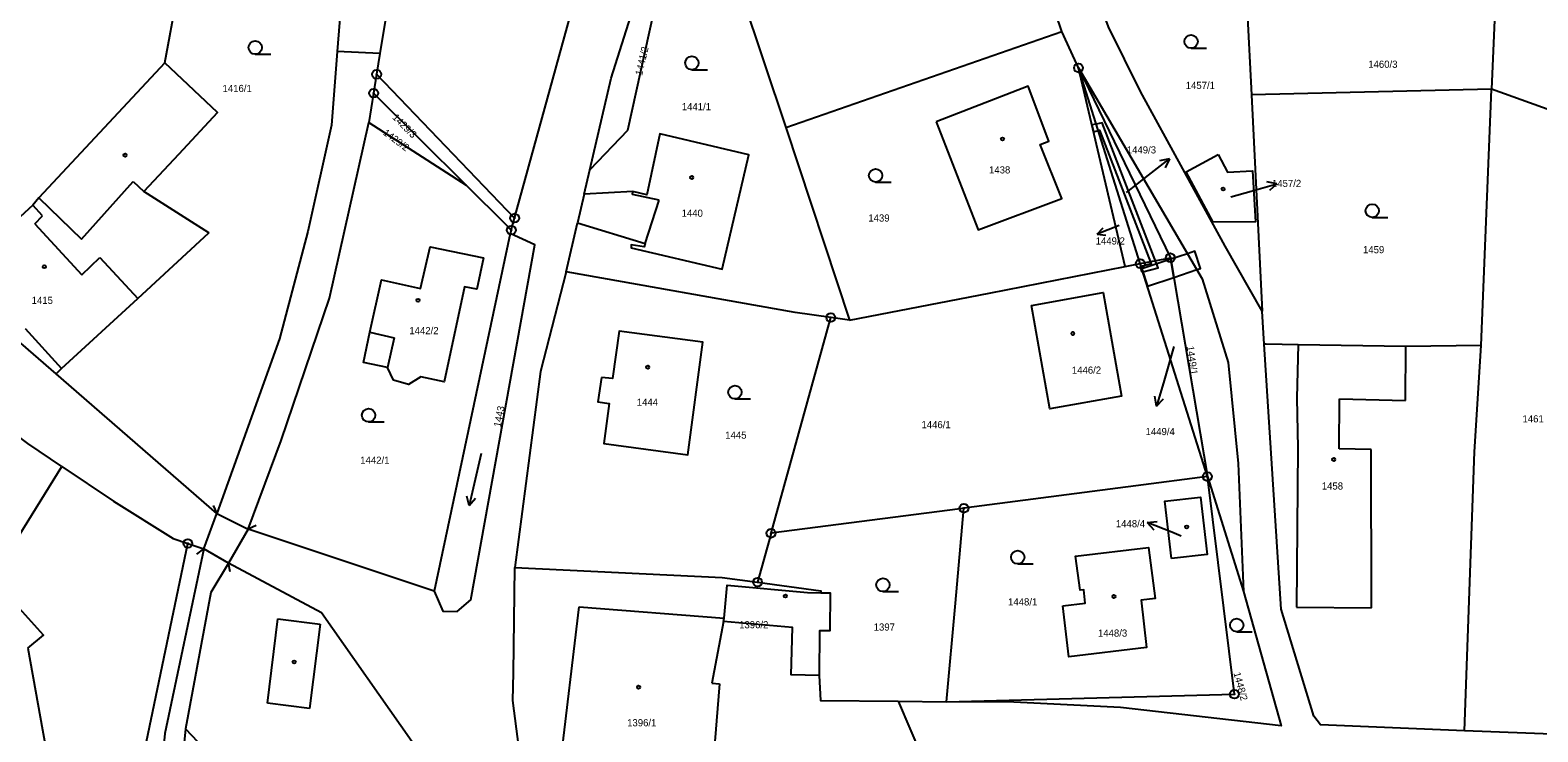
# Model space of a CAD drawing. Extents: x -587171 to -555306, y -1167727 to -1074732.
# Drawn here: x -559900.1 to -559730.7, y -1076166.3 to -1076087.4 of the extents above; entities that cross this region are included whole.
import ezdxf

# ---------------------------------------------------------------- set-up
doc = ezdxf.new("R2010")
doc.units = 0
for name, color, linetype in [('Hranice parcel', 7, 'Continuous'), ('Parcelní čísla', 7, 'Continuous'), ('Pop  PČ popisy', 7, 'Continuous'), ('Vnitřní kresba', 7, 'Continuous'), ('Věcná břemena k části', 7, 'Continuous'), ('Značky bodu BP', 7, 'Continuous'), ('Značky budov', 7, 'Continuous'), ('Značky kultur', 7, 'Continuous')]:
    doc.layers.add(name, color=color, linetype=linetype)

msp = doc.modelspace()

# ---------------------------------------------------------------- linework, layer by layer
at = {"layer": 'Hranice parcel'}
for p, q in [((-559884.99, -1076091.09), (-559876, -1076041.64)), ((-559834.85, -1076092.79), (-559826.2, -1076065.36)), ((-559784.21, -1076087.54), (-559791.91, -1076064.81)), ((-559822.86, -1076075.59), (-559815.22, -1076098.33)), ((-559865.19, -1076084.2), (-559865.63, -1076089.8)), ((-559763.38, -1076085.21), (-559762.91, -1076094.66)), ((-559735.54, -1076084.55), (-559735.95, -1076094.02)), ((-559845.7, -1076108.53), (-559839.49, -1076085.97)), ((-559815.22, -1076098.33), (-559784.21, -1076087.54)), ((-559782.34, -1076091.64), (-559784.21, -1076087.54)), ((-559860.82, -1076090.03), (-559865.63, -1076089.8)), ((-559860.82, -1076090.03), (-559861.2, -1076092.36)), ((-559861.2, -1076092.36), (-559861.54, -1076094.48)), ((-559861.2, -1076092.36), (-559845.7, -1076108.53)), ((-559777.09, -1076113.98), (-559782.34, -1076091.64)), ((-559782.34, -1076091.64), (-559772.01, -1076112.99)), ((-559775.4, -1076113.65), (-559782.34, -1076091.64)), ((-559837.24, -1076103.11), (-559834.85, -1076092.79)), ((-559735.95, -1076094.02), (-559762.91, -1076094.66)), ((-559737.09, -1076122.84), (-559735.95, -1076094.02)), ((-559722.33, -1076098.92), (-559735.95, -1076094.02)), ((-559861.54, -1076094.48), (-559862.08, -1076097.79)), ((-559851.15, -1076104.82), (-559861.54, -1076094.48)), ((-559762.91, -1076094.66), (-559761.69, -1076119.01)), ((-559862.08, -1076097.79), (-559851.15, -1076104.82)), ((-559815.22, -1076098.33), (-559808.08, -1076120.01)), ((-559837.88, -1076105.85), (-559837.24, -1076103.11)), ((-559837.88, -1076105.85), (-559838.63, -1076109.06)), ((-559846.07, -1076109.88), (-559845.7, -1076108.53)), ((-559839.91, -1076114.56), (-559838.63, -1076109.06)), ((-559846.18, -1076110.27), (-559854.72, -1076150.48)), ((-559846.07, -1076109.88), (-559846.18, -1076110.27)), ((-559777.09, -1076113.98), (-559775.4, -1076113.65)), ((-559775.4, -1076113.65), (-559772.01, -1076112.99)), ((-559767.86, -1076137.59), (-559775.4, -1076113.65)), ((-559772.01, -1076112.99), (-559767.86, -1076137.59)), ((-559816.88, -1076143.96), (-559810.17, -1076119.71)), ((-559808.08, -1076120.01), (-559810.17, -1076119.71)), ((-559761.46, -1076122.7), (-559761.69, -1076119.01)), ((-559879.16, -1076141.75), (-559897.21, -1076126.04)), ((-559767.86, -1076137.59), (-559763.79, -1076150.5)), ((-559880.6, -1076145.7), (-559879.16, -1076141.75)), ((-559882.41, -1076145.11), (-559880.6, -1076145.7)), ((-559875.64, -1076143.51), (-559877.86, -1076147.32)), ((-559854.72, -1076150.48), (-559875.64, -1076143.51)), ((-559816.88, -1076143.96), (-559818.4, -1076149.46)), ((-559802.6, -1076162.85), (-559797.17, -1076162.9)), ((-559802.6, -1076162.85), (-559799.97, -1076168.98)), ((-559882.67, -1076165.97), (-559883.32, -1076172.76)), ((-559728.16, -1076166.58), (-559738.97, -1076166.19))]:
    msp.add_line(p, q, dxfattribs=at)
for points in [[(-559855.87, -1076062.7), (-559859.56, -1076082.28), (-559860.82, -1076090.03)], [(-559826.2, -1076065.36), (-559827.24, -1076072.43), (-559833, -1076098.69), (-559837.24, -1076103.11)], [(-559761.69, -1076119.01), (-559765.87, -1076111.68), (-559775.38, -1076094.3), (-559778.98, -1076087.02), (-559785.45, -1076069.69)], [(-559865.63, -1076089.8), (-559866.28, -1076098.09), (-559868.93, -1076110.02), (-559872.1, -1076122.11), (-559879.16, -1076141.75)], [(-559884.99, -1076091.09), (-559899.17, -1076106.24), (-559899.82, -1076107.06), (-559900.76, -1076107.92), (-559907.17, -1076113.84)], [(-559897.21, -1076126.04), (-559896.61, -1076125.44), (-559888.04, -1076117.57), (-559880.04, -1076110.2), (-559882.41, -1076108.7), (-559887.36, -1076105.55), (-559883.4, -1076101.31), (-559879.06, -1076096.66), (-559884.99, -1076091.09)], [(-559782.34, -1076091.64), (-559768.44, -1076115.37), (-559765.53, -1076124.77), (-559764.41, -1076136.13), (-559763.79, -1076150.5)], [(-559798.34, -1076097.72), (-559793.61, -1076109.84), (-559784.2, -1076106.32), (-559786.63, -1076100.24), (-559785.66, -1076099.87), (-559787.99, -1076093.7), (-559798.34, -1076097.72)], [(-559875.64, -1076143.51), (-559871.92, -1076133.55), (-559866.48, -1076117.52), (-559862.08, -1076097.79)], [(-559838.63, -1076109.06), (-559831.02, -1076111.38), (-559831.14, -1076111.76), (-559832.59, -1076111.55), (-559832.59, -1076111.87), (-559822.38, -1076114.26), (-559819.38, -1076101.42), (-559829.39, -1076099.07), (-559830.85, -1076105.9), (-559832.42, -1076105.53), (-559837.88, -1076105.85)], [(-559766.66, -1076101.37), (-559765.6, -1076103.38), (-559762.77, -1076103.22), (-559762.45, -1076108.94), (-559767.19, -1076108.98), (-559770.25, -1076103.32), (-559766.66, -1076101.37)], [(-559851.15, -1076104.82), (-559846.63, -1076109.29), (-559846.07, -1076109.88)], [(-559854.72, -1076150.48), (-559853.77, -1076152.72), (-559852.14, -1076152.78), (-559850.63, -1076151.46), (-559843.43, -1076111.52), (-559846.18, -1076110.27)], [(-559849.2, -1076112.99), (-559849.94, -1076116.52), (-559851.34, -1076116.26), (-559853.61, -1076126.93), (-559856.24, -1076126.37), (-559857.6, -1076127.23), (-559859.32, -1076126.76), (-559859.96, -1076125.33), (-559862.69, -1076124.76), (-559861.98, -1076121.35), (-559860.64, -1076115.48), (-559856.27, -1076116.46), (-559855.18, -1076111.75), (-559849.2, -1076112.99)], [(-559897.21, -1076126.04), (-559901.72, -1076122.11), (-559907.17, -1076113.84)], [(-559839.91, -1076114.56), (-559842.79, -1076125.76), (-559845.67, -1076147.82)], [(-559810.17, -1076119.71), (-559814.16, -1076119.13), (-559839.91, -1076114.56)], [(-559808.08, -1076120.01), (-559792.37, -1076116.96), (-559777.09, -1076113.98)], [(-559787.62, -1076118.34), (-559779.58, -1076116.91), (-559777.52, -1076128.55), (-559785.57, -1076129.98), (-559787.62, -1076118.34)], [(-559835.94, -1076126.44), (-559836.35, -1076129.19), (-559835.06, -1076129.36), (-559835.68, -1076133.88), (-559826.23, -1076135.13), (-559824.53, -1076122.48), (-559833.95, -1076121.23), (-559834.68, -1076126.56), (-559835.94, -1076126.44)], [(-559737.09, -1076122.84), (-559745.55, -1076122.95), (-559757.64, -1076122.79), (-559761.24, -1076122.7), (-559761.46, -1076122.7)], [(-559738.97, -1076166.19), (-559755.13, -1076165.51), (-559755.91, -1076164.54), (-559759.55, -1076152.51), (-559761.46, -1076122.7)], [(-559738.97, -1076166.19), (-559737.84, -1076134.82), (-559737.09, -1076122.84)], [(-559896.56, -1076136.45), (-559900.38, -1076133.87), (-559902.61, -1076132.23)], [(-559900.38, -1076156.9), (-559898.63, -1076155.42), (-559904.38, -1076149.06), (-559896.56, -1076136.45)], [(-559896.56, -1076136.45), (-559890.78, -1076140.36), (-559884.05, -1076144.57), (-559882.41, -1076145.11)], [(-559797.17, -1076162.9), (-559764.82, -1076162.06), (-559767.86, -1076137.59)], [(-559767.86, -1076137.59), (-559775.91, -1076138.64), (-559795.21, -1076141.15)], [(-559771.87, -1076146.8), (-559772.65, -1076140.36), (-559768.63, -1076139.89), (-559767.89, -1076146.35), (-559771.87, -1076146.8)], [(-559795.21, -1076141.15), (-559795.63, -1076141.2), (-559816.88, -1076143.96)], [(-559797.17, -1076162.9), (-559796.17, -1076151.81), (-559795.21, -1076141.15)], [(-559884, -1076224.4), (-559882.97, -1076218.43), (-559883.21, -1076209.54), (-559887.76, -1076190.03), (-559888.26, -1076180.76), (-559887.42, -1076169.19), (-559882.41, -1076145.11)], [(-559880.6, -1076145.7), (-559884.99, -1076166.47), (-559886.45, -1076181.35), (-559885.78, -1076187.84), (-559883.56, -1076194.33), (-559880.18, -1076200.87), (-559872.79, -1076210.53), (-559872.01, -1076213.63), (-559872.94, -1076226.45), (-559877.73, -1076234.53)], [(-559784.11, -1076152.12), (-559781.57, -1076151.82), (-559781.74, -1076150.33), (-559782.14, -1076150.37), (-559782.68, -1076146.53), (-559774.48, -1076145.58), (-559773.74, -1076151.29), (-559775.29, -1076151.5), (-559774.71, -1076156.81), (-559783.43, -1076157.84), (-559784.11, -1076152.12)], [(-559877.86, -1076147.32), (-559879.81, -1076150.61), (-559882.67, -1076165.97)], [(-559857.26, -1076167.36), (-559867.39, -1076152.91), (-559877.86, -1076147.32)], [(-559840.08, -1076180.86), (-559843.68, -1076174.89), (-559844.71, -1076172.04), (-559845.91, -1076162.75), (-559845.81, -1076159.66), (-559845.67, -1076147.82)], [(-559845.67, -1076147.82), (-559822.39, -1076148.92), (-559818.4, -1076149.46)], [(-559811.49, -1076159.94), (-559814.62, -1076159.89), (-559814.49, -1076154.56), (-559822.21, -1076153.87), (-559822.14, -1076153.5), (-559821.81, -1076149.79), (-559812.77, -1076150.62), (-559811.3, -1076150.65)], [(-559818.4, -1076149.46), (-559811.3, -1076150.42), (-559811.3, -1076150.65)], [(-559811.3, -1076150.65), (-559810.25, -1076150.68), (-559810.29, -1076154.94), (-559811.43, -1076154.93), (-559811.49, -1076159.94)], [(-559763.79, -1076150.5), (-559759.55, -1076165.6), (-559777.62, -1076163.54), (-559789.59, -1076162.96), (-559797.17, -1076162.9)], [(-559900.38, -1076156.9), (-559890.01, -1076214.69), (-559884, -1076224.4)], [(-559811.49, -1076159.94), (-559811.33, -1076162.78), (-559802.6, -1076162.85)], [(-559882.67, -1076165.97), (-559880.03, -1076168.77), (-559881.21, -1076179.06), (-559868.73, -1076181.16), (-559868.01, -1076175.07), (-559867.5, -1076175.13), (-559863.36, -1076174.42), (-559857.26, -1076167.36)]]:
    msp.add_lwpolyline(points, dxfattribs=at)
at = {"layer": 'Pop  PČ popisy'}
for p, q in [((-559774.49, -1076103.72), (-559772.12, -1076101.87)), ((-559772.12, -1076101.87), (-559773.22, -1076102.09)), ((-559772.12, -1076101.87), (-559772.61, -1076102.88)), ((-559776.93, -1076105.64), (-559774.49, -1076103.72)), ((-559760.06, -1076104.66), (-559761.16, -1076104.46)), ((-559765.22, -1076106.15), (-559762.94, -1076105.49)), ((-559762.94, -1076105.49), (-559760.06, -1076104.66)), ((-559760.06, -1076104.66), (-559760.88, -1076105.42)), ((-559777.78, -1076109.36), (-559780.23, -1076110.35)), ((-559780.23, -1076110.35), (-559779.58, -1076109.61)), ((-559780.23, -1076110.35), (-559779.25, -1076110.43)), ((-559771.63, -1076122.95), (-559772.73, -1076126.78)), ((-559772.73, -1076126.78), (-559773.56, -1076129.67)), ((-559773.56, -1076129.67), (-559773.76, -1076128.56)), ((-559773.56, -1076129.67), (-559772.8, -1076128.84)), ((-559774.62, -1076142.74), (-559773.51, -1076142.65)), ((-559771.84, -1076143.86), (-559774.62, -1076142.74)), ((-559774.62, -1076142.74), (-559773.88, -1076143.57)), ((-559770.81, -1076144.28), (-559771.84, -1076143.86))]:
    msp.add_line(p, q, dxfattribs=at)
at = {"layer": 'Vnitřní kresba'}
for p, q in [((-559894.37, -1076110.88), (-559888.56, -1076104.43)), ((-559888.56, -1076104.43), (-559887.36, -1076105.55)), ((-559832.46, -1076105.86), (-559832.42, -1076105.53)), ((-559829.44, -1076106.51), (-559832.46, -1076105.86)), ((-559898.73, -1076108.27), (-559899.82, -1076107.06)), ((-559899.17, -1076106.24), (-559894.37, -1076110.88)), ((-559831.02, -1076111.38), (-559829.44, -1076106.51)), ((-559899.6, -1076109.18), (-559898.73, -1076108.27)), ((-559899.6, -1076109.18), (-559894.33, -1076114.9)), ((-559894.33, -1076114.9), (-559892.3, -1076112.97)), ((-559892.3, -1076112.97), (-559888.04, -1076117.57)), ((-559900.69, -1076120.95), (-559896.61, -1076125.44)), ((-559861.98, -1076121.35), (-559859.22, -1076121.99)), ((-559859.22, -1076121.99), (-559859.96, -1076125.33)), ((-559757.64, -1076122.79), (-559757.81, -1076128.72)), ((-559745.61, -1076129.04), (-559745.55, -1076122.95)), ((-559757.81, -1076128.72), (-559757.68, -1076134.4)), ((-559753.06, -1076134.48), (-559753.02, -1076128.85)), ((-559753.02, -1076128.85), (-559745.61, -1076129.04)), ((-559757.68, -1076134.4), (-559757.86, -1076152.28)), ((-559749.46, -1076134.53), (-559753.06, -1076134.48)), ((-559749.43, -1076152.35), (-559749.46, -1076134.53)), ((-559879.58, -1076140.84), (-559879.16, -1076141.75)), ((-559879.16, -1076141.75), (-559875.64, -1076143.51)), ((-559874.73, -1076143.1), (-559875.64, -1076143.51)), ((-559881.4, -1076146.3), (-559880.6, -1076145.7)), ((-559877.86, -1076147.32), (-559880.6, -1076145.7)), ((-559877.64, -1076148.29), (-559877.86, -1076147.32)), ((-559873.47, -1076163.07), (-559872.29, -1076153.57)), ((-559872.29, -1076153.57), (-559867.55, -1076154.19)), ((-559840.95, -1076173.22), (-559838.44, -1076152.23)), ((-559838.44, -1076152.23), (-559822.14, -1076153.5)), ((-559757.86, -1076152.28), (-559749.43, -1076152.35)), ((-559867.55, -1076154.19), (-559868.73, -1076163.68)), ((-559822.21, -1076153.87), (-559823.52, -1076160.82)), ((-559822.66, -1076160.89), (-559823.84, -1076175.31)), ((-559823.52, -1076160.82), (-559822.66, -1076160.89)), ((-559868.73, -1076163.68), (-559873.47, -1076163.07))]:
    msp.add_line(p, q, dxfattribs=at)
at = {"layer": 'Věcná břemena k části'}
for points in [[(-559780.12, -1076098.69), (-559779.98, -1076098.66), (-559774.19, -1076113.66), (-559775.3, -1076113.96), (-559775.11, -1076114.56), (-559773.37, -1076114.13), (-559779.67, -1076097.8), (-559780.35, -1076097.95), (-559780.83, -1076098.06), (-559780.65, -1076098.82)], [(-559770.1, -1076112.53), (-559771.98, -1076113.16), (-559771.64, -1076115.19), (-559769.05, -1076114.32), (-559768.63, -1076114.18), (-559769.28, -1076112.25)], [(-559775.24, -1076114.59), (-559775.11, -1076114.56), (-559775.3, -1076113.96), (-559775.4, -1076113.99)], [(-559771.64, -1076115.19), (-559771.98, -1076113.16), (-559775.21, -1076114.25), (-559774.6, -1076116.19)]]:
    msp.add_lwpolyline(points, close=True, dxfattribs=at)
at = {"layer": 'Značky bodu BP'}
for centre, radius in [((-559861.2, -1076092.36), 0.5), ((-559861.2, -1076092.36), 0.0303), ((-559782.34, -1076091.64), 0.5), ((-559782.34, -1076091.64), 0.0303), ((-559861.54, -1076094.48), 0.5), ((-559861.54, -1076094.48), 0.0303), ((-559846.07, -1076109.88), 0.5), ((-559845.7, -1076108.53), 0.5), ((-559845.7, -1076108.53), 0.0303), ((-559846.07, -1076109.88), 0.0303), ((-559772.01, -1076112.99), 0.5), ((-559772.01, -1076112.99), 0.0303), ((-559775.4, -1076113.65), 0.5), ((-559775.4, -1076113.65), 0.0303), ((-559810.17, -1076119.71), 0.5), ((-559810.17, -1076119.71), 0.0303), ((-559767.86, -1076137.59), 0.5), ((-559767.86, -1076137.59), 0.0303), ((-559795.21, -1076141.15), 0.5), ((-559795.21, -1076141.15), 0.0303), ((-559816.88, -1076143.96), 0.5), ((-559882.41, -1076145.11), 0.5), ((-559882.41, -1076145.11), 0.0303), ((-559816.88, -1076143.96), 0.0303), ((-559818.4, -1076149.46), 0.5), ((-559818.4, -1076149.46), 0.0303), ((-559764.82, -1076162.06), 0.5), ((-559764.82, -1076162.06), 0.0303)]:
    msp.add_circle(centre, radius, dxfattribs=at)
at = {"layer": 'Značky budov'}
for centre in [(-559790.88, -1076099.64), (-559889.47, -1076101.45), (-559825.8, -1076103.96), (-559766.09, -1076105.26), (-559898.54, -1076114), (-559856.55, -1076117.77), (-559782.97, -1076121.51), (-559830.74, -1076125.29), (-559753.66, -1076135.67), (-559770.18, -1076143.26), (-559815.27, -1076151.03), (-559778.36, -1076151.07), (-559870.47, -1076158.44), (-559831.76, -1076161.27)]:
    msp.add_circle(centre, 0.175, dxfattribs=at)
at = {"layer": 'Značky kultur'}
for p, q in [((-559874.84, -1076090.1), (-559873.09, -1076090.1)), ((-559769.69, -1076089.43), (-559767.94, -1076089.43)), ((-559825.78, -1076091.84), (-559824.03, -1076091.84)), ((-559805.13, -1076104.49), (-559803.38, -1076104.49)), ((-559749.33, -1076108.45), (-559747.58, -1076108.45)), ((-559820.94, -1076128.86), (-559819.19, -1076128.86)), ((-559862.1, -1076131.45), (-559860.35, -1076131.45)), ((-559849.44, -1076135.01), (-559850.79, -1076140.86)), ((-559850.79, -1076140.86), (-559851.06, -1076139.79)), ((-559850.79, -1076140.86), (-559850.08, -1076140.02)), ((-559789.17, -1076147.41), (-559787.42, -1076147.41)), ((-559804.31, -1076150.52), (-559802.56, -1076150.52)), ((-559764.56, -1076155.05), (-559762.81, -1076155.05))]:
    msp.add_line(p, q, dxfattribs=at)
for centre in [(-559874.84, -1076089.35), (-559769.69, -1076088.68), (-559825.78, -1076091.09), (-559805.13, -1076103.74), (-559749.33, -1076107.7), (-559820.94, -1076128.11), (-559862.1, -1076130.7), (-559789.17, -1076146.66), (-559804.31, -1076149.77), (-559764.56, -1076154.3)]:
    msp.add_circle(centre, 0.75, dxfattribs=at)

# ---------------------------------------------------------------- texts
at = {"layer": 'Parcelní čísla'}
for s, rotation, p in [('1441/2', 77, (-559831.37, -1076092.55)), ('1429/3', 315, (-559859.5, -1076097.28)), ('1429/2', 323, (-559860.55, -1076099.08)), ('1449/1', 278, (-559770.18, -1076122.95)), ('1443', 79, (-559847.27, -1076132.08)), ('1448/2', 285, (-559764.93, -1076159.69))]:
    msp.add_text(s, height=0.803, rotation=rotation, dxfattribs=at).set_placement(p)
for s, p in [('1460/3', (-559749.78, -1076091.63)), ('1416/1', (-559878.51, -1076094.35)), ('1457/1', (-559770.29, -1076094.01)), ('1441/1', (-559826.91, -1076096.4)), ('1449/3', (-559776.91, -1076101.26)), ('1438', (-559792.39, -1076103.51)), ('1457/2', (-559760.6, -1076105.03)), ('1440', (-559826.93, -1076108.38)), ('1439', (-559805.95, -1076108.92)), ('1449/2', (-559780.41, -1076111.5)), ('1459', (-559750.37, -1076112.48)), ('1415', (-559899.96, -1076118.18)), ('1442/2', (-559857.52, -1076121.58)), ('1446/2', (-559783.08, -1076126.02)), ('1444', (-559831.97, -1076129.63)), ('1446/1', (-559799.98, -1076132.15)), ('1461', (-559732.45, -1076131.5)), ('1445', (-559822.03, -1076133.33)), ('1449/4', (-559774.8, -1076132.93)), ('1442/1', (-559863.04, -1076136.15)), ('1458', (-559755, -1076139.05)), ('1448/4', (-559778.14, -1076143.29)), ('1448/1', (-559790.25, -1076152.08)), ('1396/2', (-559820.47, -1076154.65)), ('1397', (-559805.35, -1076154.91)), ('1448/3', (-559780.15, -1076155.59)), ('1396/1', (-559833.05, -1076165.67))]:
    msp.add_text(s, height=0.803, dxfattribs=at).set_placement(p)

doc.saveas('drawing.dxf')
